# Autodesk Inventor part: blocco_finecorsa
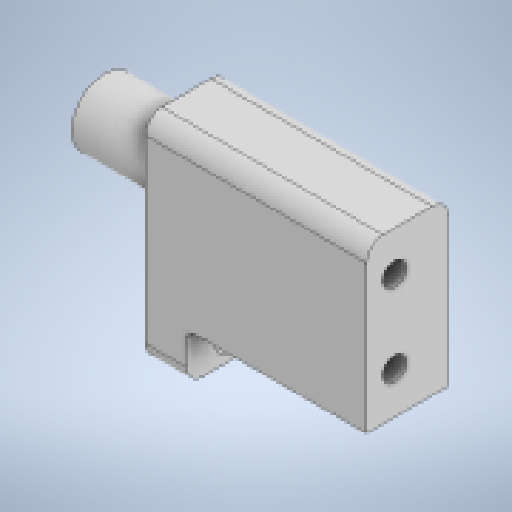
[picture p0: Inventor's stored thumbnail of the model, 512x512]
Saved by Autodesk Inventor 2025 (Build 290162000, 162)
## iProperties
Created: 2026-03
Part Number: blocco_finecorsa
Material: Generico
Document SubType Name: Modeling
Designer: Ryzen5700u
Density: 1 g/cm^3
Appearance: Default
Author: Ryzen5700u
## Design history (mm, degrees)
sketch "Schizzo1"
  geometry: L1 (10, 5)-(-10, 5); L2 (-10, 5)-(-10, -5); L3 (-10, -5)-(10, -5); L4 (10, -5)-(10, 5); L5 (10, 5)-(-10, -5); L6 (-10, 5)-(10, -5); 1 further point
  constraints: 12 end point, 2 midpoint, 2 parallel, 1 horizontal, 1 perpendicular
  dimensions: "d0" = 20 distance of L3.end L2.end; "d1" = 10 distance of L2.end L1.end
extrude "Estrusione1" new body sketch "Schizzo1" distance "d2" = 27; taper "d3" = 0 deg
sketch "Schizzo2"
  geometry: C1 r 4 at (0, 1); 1 further point
  constraints: 1 centre point
  dimensions: "d4" = 8 diameter of C1; "d5" = -1 distance of point (0, 0) C1.centre
extrude "Estrusione2" join sketch "Schizzo2" distance "d6" = 10; taper "d7" = 0 deg
sketch "Schizzo3"
  geometry: C1 r 1.25 at (-1.6, 5.125) reference; C2 r 1.25 at (-1.6, -4.875) reference; 1 further point
hole "Foro1" sketch "Schizzo3" at (-1.6, 5.125), (-1.6, -4.875) diameter "d9" = 2.9; stored, may be unused: countersink angle "d13" = 90 deg, drill point angle "d15" = 118 deg; dims "d10" = 6, "d11" = 5.5, "d12" = 2.9, "d14" = 8
sketch "Schizzo4"
  geometry: L1 (5, -10)-(-5, -10) reference; L2 (5, 10)-(5, -10) reference; L3 (-5, 10)-(5, 10) reference; L4 (-5, -10)-(-5, 10) reference; L5 (5, -10)-(-5, -10) reference; L6 (5, -10)-(-5, -10); L7 (-5, -10)-(-5, -16); L8 (-5, -16)-(5, -16); L9 (5, -16)-(5, -10); C1 r 4 at (0, 1) reference; 2 further points
  constraints: 8 end point, 2 parallel, 1 horizontal, 1 perpendicular
  dimensions: "d16" = 6 distance of L7.end L6.end
extrude "Estrusione3" join sketch "Schizzo4" distance "d17" = 5; taper "d18" = 0 deg
fillet "Raccordo2" dims "d19" = 1
sketch "Schizzo5"
  geometry: L1 (-5, -16)-(5, -16) reference; 2 further points
  dimensions: "d27" = 2.5 distance from line of L1 point (0, -13.5)
hole "Foro2" sketch "Schizzo5" at (0, -13.5) diameter "d20" = 2.9; stored, may be unused: countersink angle "d24" = 90 deg, drill point angle "d26" = 118 deg; dims "d21" = 6, "d22" = 4, "d23" = 2, "d25" = 8
fillet "Raccordo3" dims "d28" = 2
node "Solido1"
node "Riferimento1"
node "Riferimento2"
node "Linea chiusa proiettata1"
